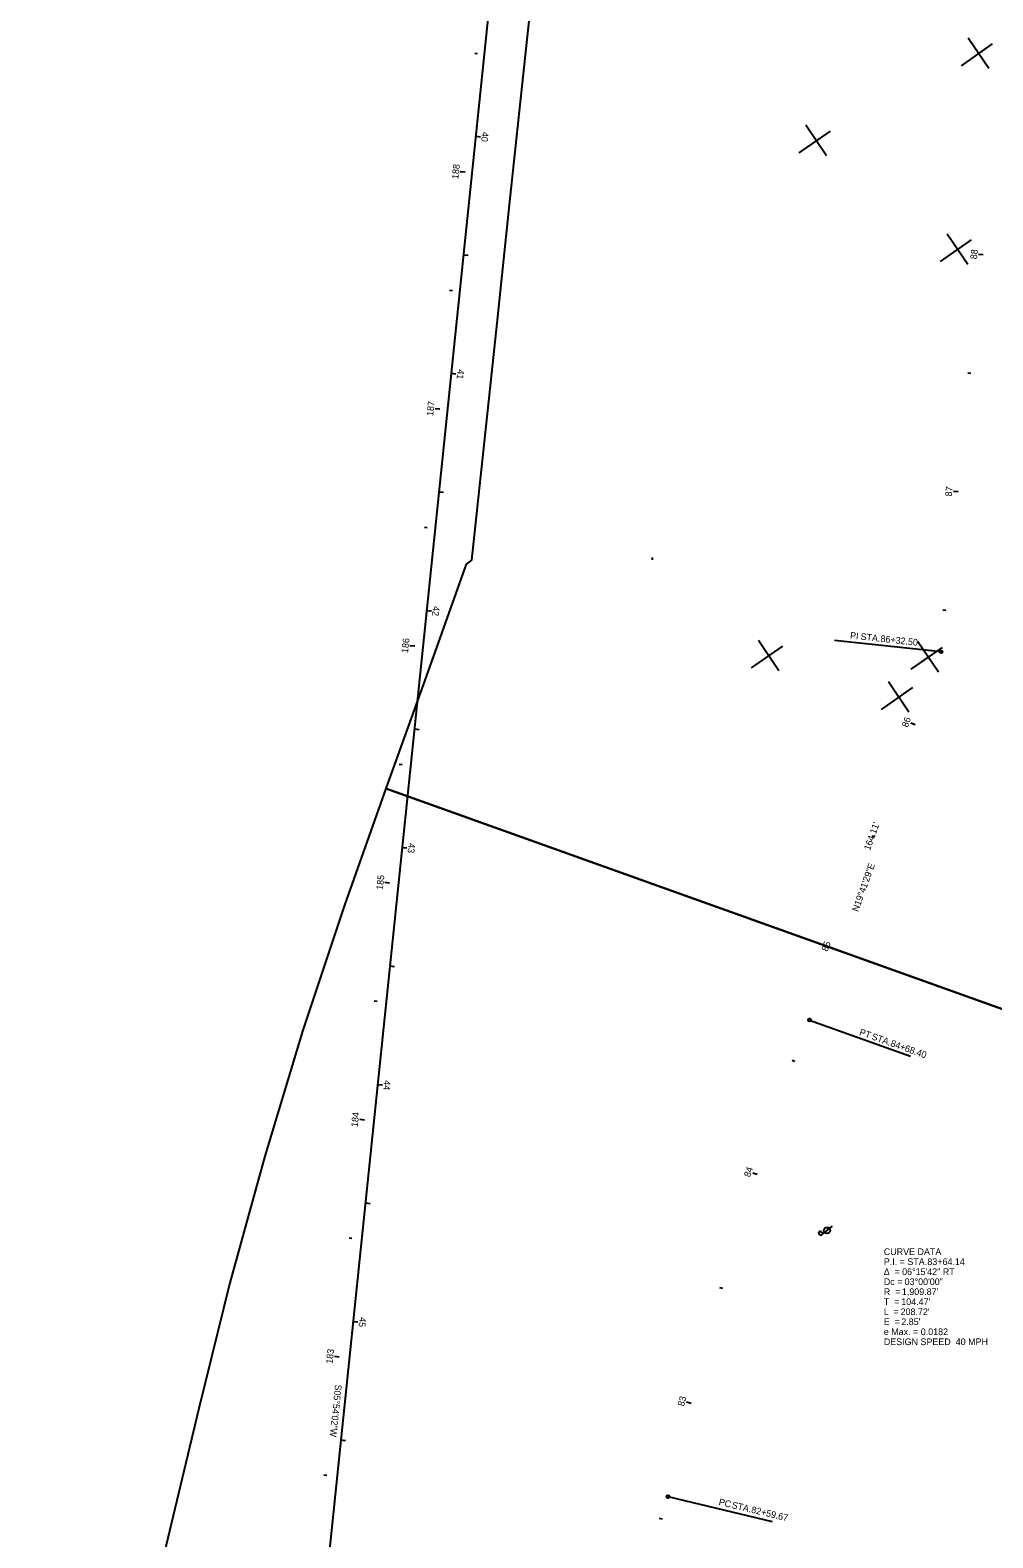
# Model space of a CAD drawing. Extents: x 172043 to 172958, y 249504 to 260295.
# Drawn here: x 172171 to 172575, y 255155 to 255788 of the extents above; entities that cross this region are included whole.
import ezdxf

# ---------------------------------------------------------------- set-up
doc = ezdxf.new("R2010")
doc.units = 0
for name, color, linetype in [('BD_X_Building', 7, 'Continuous'), ('DR_X_Storm_Sewer', 7, 'Continuous'), ('PV_X_EOP', 7, 'Continuous'), ('RD_X_Concrete_Barrier', 7, 'Continuous'), ('RS_Raster1', 7, 'Continuous'), ('RW_X_CL_100_Bearings', 7, 'Continuous'), ('RW_X_CL_100_Cardinal_Points', 7, 'Continuous'), ('RW_X_CL_100_Curve_Data', 7, 'Continuous'), ('RW_X_CL_100_Stations', 7, 'Continuous'), ('SC_Scratch1', 7, 'Continuous'), ('UT_X_Electric_Cells', 7, 'Continuous')]:
    doc.layers.add(name, color=color, linetype=linetype)

msp = doc.modelspace()

# ---------------------------------------------------------------- linework, layer by layer
at = {"layer": 'BD_X_Building'}
for p, q in [((172562.16, 255772.75), (172575.26, 255781.89)), ((172573.67, 255771.53), (172565.01, 255784.28)), ((172494.07, 255736.22), (172507.17, 255745.35)), ((172505.58, 255735), (172496.93, 255747.75)), ((172553.33, 255690.54), (172566.43, 255699.67)), ((172564.84, 255689.31), (172556.19, 255702.06)), ((172474.11, 255520.04), (172487.22, 255529.18)), ((172485.62, 255518.82), (172476.97, 255531.57)), ((172541.08, 255519.53), (172554.18, 255528.67)), ((172552.59, 255518.31), (172543.94, 255531.06)), ((172528.64, 255502.65), (172541.74, 255511.79)), ((172540.15, 255501.43), (172531.5, 255514.18))]:
    msp.add_line(p, q, dxfattribs=at)
at = {"layer": 'DR_X_Storm_Sewer'}
for points in [[(172320.75, 255469.43), (172697.36, 255334.65), (172714.21, 255381.73), (172731.06, 255428.8), (172754.44, 255523.13), (172759.7, 255572.85), (172764.97, 255622.58), (172770.23, 255672.3), (172775.5, 255722.02), (172780.76, 255771.74), (172786.03, 255821.46), (172791.29, 255871.19), (172393.52, 255913.31), (172388.25, 255863.59), (172382.99, 255813.87), (172377.72, 255764.14), (172372.46, 255714.42), (172367.19, 255664.7), (172361.93, 255614.98), (172356.66, 255565.26), (172354.45, 255563.58), (172337.6, 255516.51)], [(172184.15, 254963.66), (172574.32, 254875.56), (172585.22, 254922.95), (172596.48, 254970.85), (172608.01, 255019.19), (172619.62, 255067.83), (172631.23, 255116.46), (172642.23, 255160.89), (172654.11, 255204.05), (172667.12, 255246.88), (172681.24, 255289.36), (172697.36, 255334.65), (172320.75, 255469.43), (172303.35, 255420.51), (172285.92, 255368.09), (172269.88, 255315.24), (172255.22, 255261.99), (172242.17, 255209.36), (172230.56, 255160.73), (172218.95, 255112.1), (172207.28, 255063.17), (172195.65, 255013.72)]]:
    msp.add_lwpolyline(points, close=True, dxfattribs=at)
at = {"layer": 'PV_X_EOP'}
for p, q in [((172359.19, 255777.79), (172358, 255777.91)), ((172353.92, 255728.07), (172351.93, 255728.28)), ((172348.64, 255678.34), (172347.45, 255678.47)), ((172343.36, 255628.62), (172341.37, 255628.84)), ((172338.09, 255578.9), (172336.89, 255579.03)), ((172332.81, 255529.18), (172330.82, 255529.39)), ((172327.53, 255479.46), (172326.34, 255479.59)), ((172322.26, 255429.74), (172320.27, 255429.95)), ((172316.98, 255380.02), (172315.79, 255380.15)), ((172311.7, 255330.3), (172309.71, 255330.51)), ((172306.42, 255280.58), (172305.23, 255280.71)), ((172301.15, 255230.86), (172299.16, 255231.07)), ((172295.87, 255181.14), (172294.68, 255181.26))]:
    msp.add_line(p, q, dxfattribs=at)
at = {"layer": 'RD_X_Concrete_Barrier'}
for p, q in [((172503.2, 255281.91), (172502.52, 255282.41)), ((172503.2, 255281.91), (172508.03, 255285.82)), ((172504.23, 255282.74), (172503.27, 255283.44))]:
    msp.add_line(p, q, dxfattribs=at)
msp.add_circle((172505.78, 255284), 1.3, dxfattribs=at)
msp.add_arc((172502.88, 255282.94), 0.638, 52.83233, 235.07893, dxfattribs=at)
at = {"layer": 'RW_X_CL_100_Bearings'}
for p, q in [((172553.71, 255526.79), (172508.96, 255531.53)), ((172498.41, 255372.28), (172540.78, 255357.12)), ((172438.95, 255172.32), (172482.72, 255161.87))]:
    msp.add_line(p, q, dxfattribs=at)
for centre in [(172553.71, 255526.79), (172498.41, 255372.28), (172438.95, 255172.32)]:
    msp.add_circle(centre, 0.6, dxfattribs=at)
at = {"layer": 'RW_X_CL_100_Stations'}
for p, q in [((172571.34, 255693.36), (172569.36, 255693.57)), ((172566.08, 255643.64), (172564.89, 255643.76)), ((172560.81, 255593.92), (172558.82, 255594.13)), ((172555.55, 255544.19), (172554.35, 255544.32)), ((172542.75, 255496.19), (172540.87, 255496.87)), ((172525.91, 255449.12), (172524.78, 255449.52)), ((172509.06, 255402.04), (172507.18, 255402.71)), ((172492.29, 255354.93), (172491.16, 255355.33)), ((172476.52, 255307.49), (172474.62, 255308.1)), ((172462, 255259.65), (172460.84, 255259.98)), ((172448.73, 255211.44), (172446.79, 255211.95)), ((172436.7, 255162.91), (172435.53, 255163.19))]:
    msp.add_line(p, q, dxfattribs=at)
at = {"layer": 'SC_Scratch1'}
for p, q in [((172428.67, 256423.35), (172177.28, 253990.91)), ((172409.1, 256234.03), (172171.47, 253934.66)), ((172358.37, 255743.16), (172360.36, 255742.96)), ((172358.37, 255743.16), (172360.36, 255742.96)), ((172353.23, 255693.43), (172355.22, 255693.22)), ((172348.09, 255643.69), (172350.08, 255643.49)), ((172348.09, 255643.69), (172350.08, 255643.49)), ((172342.95, 255593.96), (172344.94, 255593.75)), ((172337.81, 255544.22), (172339.8, 255544.02)), ((172337.81, 255544.22), (172339.8, 255544.02)), ((172332.67, 255494.49), (172334.66, 255494.28)), ((172327.53, 255444.75), (172329.52, 255444.55)), ((172327.53, 255444.75), (172329.52, 255444.55)), ((172322.39, 255395.02), (172324.38, 255394.81)), ((172317.25, 255345.28), (172319.24, 255345.08)), ((172317.25, 255345.28), (172319.24, 255345.08)), ((172312.11, 255295.55), (172314.1, 255295.34)), ((172306.97, 255245.81), (172308.96, 255245.61)), ((172306.97, 255245.81), (172308.96, 255245.61)), ((172301.83, 255196.08), (172303.82, 255195.87))]:
    msp.add_line(p, q, dxfattribs=at)
at = {"layer": 'UT_X_Electric_Cells'}
msp.add_line((172432.56, 255565.4), (172432.58, 255566.43), dxfattribs=at)

# ---------------------------------------------------------------- texts
at = {"layer": 'PV_X_EOP'}
for s, p in [('188', (172351.09, 255725.1)), ('187', (172340.53, 255625.66)), ('186', (172329.98, 255526.21)), ('185', (172319.43, 255426.82)), ('184', (172308.87, 255327.3)), ('183', (172298.32, 255227.94))]:
    msp.add_text(s, height=2.8, rotation=83.94188, dxfattribs=at).set_placement(p)
at = {"layer": 'RS_Raster1'}
msp.add_text('N19°41\'29"E', height=2.8, rotation=70.30874, dxfattribs=at).set_placement((172518.81, 255417.53))
at = {"layer": 'RW_X_CL_100_Bearings'}
for s, rotation, p in [('PI', 353.95499, (172515.34, 255532.37)), (' STA. ', 353.95499, (172518.71, 255532.01)), ('86+32.50', 353.95499, (172528.11, 255531.01)), ('PT', 340.30874, (172519.08, 255366.11)), (' STA. ', 340.30874, (172523.24, 255364.62)), ('84+68.40', 340.30874, (172532.14, 255361.44)), ('PC', 346.57039, (172460.14, 255168.86)), (' STA. ', 346.57039, (172464.6, 255167.79)), ('82+59.67', 346.57039, (172473.79, 255165.6))]:
    msp.add_text(s, height=2.8, rotation=rotation, dxfattribs=at).set_placement(p)
at = {"layer": 'RW_X_CL_100_Cardinal_Points'}
for s, p in [('CURVE DATA', (172529.59, 255273.69)), ('P.I. = STA. ', (172529.59, 255269.49)), ('06°15\'42" RT', (172537.27, 255265.29)), ('83+64.14', (172547.86, 255269.49)), ('Δ  = ', (172529.59, 255265.29)), ('Dc = ', (172529.59, 255261.09)), ('03°00\'00"', (172538.33, 255261.09)), ('T  = ', (172529.59, 255252.69)), ('R  = ', (172529.59, 255256.89)), ("104.47'", (172536.93, 255252.69)), ("1,909.87'", (172537.17, 255256.89)), ('L  = ', (172529.59, 255248.49)), ("208.72'", (172536.63, 255248.49)), ('e Max. = 0.0182', (172529.59, 255240.09)), ('E  = ', (172529.59, 255244.29)), ("2.85'", (172536.93, 255244.29)), ('DESIGN SPEED  40 MPH', (172529.59, 255235.89))]:
    msp.add_text(s, height=2.8, dxfattribs=at).set_placement(p)
at = {"layer": 'RW_X_CL_100_Curve_Data'}
msp.add_text("164.11'", height=2.8, rotation=70.30874, dxfattribs=at).set_placement((172523.77, 255443.26))
at = {"layer": 'RW_X_CL_100_Stations'}
for s, rotation, p in [('88', 83.95499, (172568.63, 255691.42)), ('87', 83.95499, (172558.09, 255591.89)), ('86', 70.30874, (172539.64, 255494.92)), ('85', 70.30874, (172505.97, 255400.82)), ('84', 72.36058, (172473.49, 255306.19)), ('83', 75.36056, (172445.76, 255209.99))]:
    msp.add_text(s, height=2.8, rotation=rotation, dxfattribs=at).set_placement(p)
at = {"layer": 'SC_Scratch1'}
for s, p in [('40', (172361.09, 255745.12)), ('41', (172350.79, 255645.46)), ('42', (172340.52, 255546.12)), ('43', (172330.24, 255446.64)), ('44', (172319.96, 255347.17)), ('45', (172309.68, 255247.73)), ('S05°54\'02"W', (172299.42, 255219.45))]:
    msp.add_text(s, height=2.8, rotation=264.09958, dxfattribs=at).set_placement(p)

doc.saveas('drawing.dxf')
